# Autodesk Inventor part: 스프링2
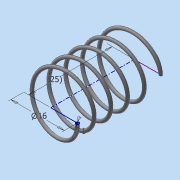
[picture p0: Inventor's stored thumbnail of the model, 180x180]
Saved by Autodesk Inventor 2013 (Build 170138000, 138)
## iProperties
Created: 2015-11
Part Number: 스프링2
Material: 일반
Document SubType Name: Modeling
Designer: dgall
Density: 1 g/cm^3
Author: dgall
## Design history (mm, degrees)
sketch "스케치1"
  geometry: L1 (8, 0)-(0, 0); L2 (0, 0)-(0, 26); L3 (0, 26)-(8, 26); C1 r 0.5 at (8, 0)
  constraints: 6 end point, 1 centre point, 1 coincident, 1 horizontal, 1 parallel, 1 perpendicular, 1 vertical alignment
  dimensions: "d5" = 16 diameter of L1.start L2; "d7" = 26 distance of L1.end L2.end (derived); "d8" = 1 diameter of C1
feature "코일1" pitch "d9" = 10; turns "d11" = 5; dims "d10" = 26 (= d7), "d12" = 0, angle "d13" = 90 deg, angle "d14" = 90 deg, "d15" = 0, "d16" = 0
sketch "스케치2"
  geometry: L1 (-10, 0)-(10, 0); L2 (10, 0)-(10, -5); L3 (10, -5)-(-10, -5); L4 (-10, -5)-(-10, 0); L5 (-10, 30)-(10, 30); L6 (10, 30)-(10, 25); L7 (10, 25)-(-10, 25); L8 (-10, 25)-(-10, 30); 4 further points
  constraints: 16 end point, 4 parallel, 3 midpoint, 2 horizontal, 2 perpendicular, 1 coincident, 1 vertical alignment
  dimensions: "d17" = 25 distance between parallel lines of L7 L1; "d18" = 5 distance of L7.end L5.start; "d19" = 5 distance of L3.end L1.start; "d20" = 20 distance of L2.end L3.end; "d21" = 20 distance of L5.start L5.end
extrude "돌출1" cut sketch "스케치2" stored distance "d22" = 30; taper "d23" = 0 deg
node "솔리드1"
